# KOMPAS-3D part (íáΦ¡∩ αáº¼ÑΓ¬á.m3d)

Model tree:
1. Эскиз:1
2. Операция выдавливания:1
     Расстояние 1 = 2
3. Смещенная плоскость:1
     Расстояние = 11.1
4. Смещенная плоскость:2
     Расстояние = 11.1
5. Смещенная плоскость:3
     Расстояние = 11.1
6. Смещенная плоскость:4
     Расстояние = 11.1
7. Смещенная плоскость:5
     Расстояние = 11.1
8. Смещенная плоскость:6
     Расстояние = 11.1
9. Смещенная плоскость:7
     Расстояние = 11.1
10. Смещенная плоскость:15
     Расстояние = 11
11. Смещенная плоскость:16
     Расстояние = 11
12. Смещенная плоскость:17
     Расстояние = 11
13. Смещенная плоскость:18
     Расстояние = 11
14. Смещенная плоскость:19
     Расстояние = 11
15. Смещенная плоскость:20
     Расстояние = 11
16. Смещенная плоскость:21
     Расстояние = 11
17. Смещенная плоскость:22
     Расстояние = 11
18. Смещенная плоскость:23
     Расстояние = 11
19. Смещенная плоскость:24
     Расстояние = 11
20. Смещенная плоскость:25
     Расстояние = 11
21. Смещенная плоскость:26
     Расстояние = 11
22. Смещенная плоскость:27
     Расстояние = 11
23. Смещенная плоскость:28
     Расстояние = 5.4
24. Смещенная плоскость:29
     Расстояние = 5.4
25. Смещенная плоскость:30
     Расстояние = 5.4
26. Смещенная плоскость:31
     Расстояние = 5.4
27. Смещенная плоскость:32
     Расстояние = 5.4
28. Смещенная плоскость:33
     Расстояние = 5.4
29. Смещенная плоскость:34
     Расстояние = 5.4
30. Эскиз:2
31. Эскиз:3
32. Эскиз:4
33. Эскиз:5
34. Эскиз:6
35. Эскиз:7
36. Эскиз:8
37. Эскиз:9
38. Эскиз:10
39. Эскиз:11
40. Эскиз:12
41. Эскиз:13
42. Эскиз:14
43. Эскиз:15
44. Эскиз:16
45. Эскиз:17
46. Эскиз:18
47. Эскиз:19
48. Эскиз:20
49. Эскиз:21
50. Эскиз:22
51. Эскиз:23
52. Эскиз:24
53. Эскиз:25
54. Эскиз:26
55. Эскиз:27
56. Эскиз:28
57. Эскиз:29
58. Эскиз:30

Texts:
  Сплав АЛ8  ГОСТ 1583-93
